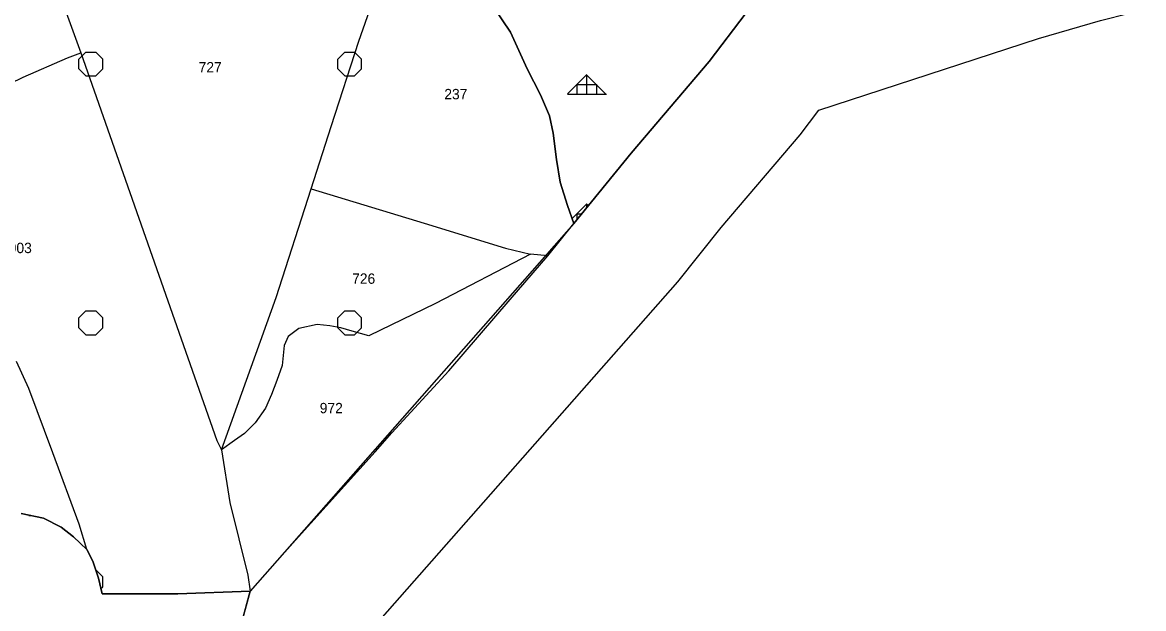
# Model space of a CAD drawing. Extents: x 410727 to 412947, y 4463506 to 4466382.
# Drawn here: x 412194.6 to 412627.7, y 4465187.2 to 4465413.6 of the extents above; entities that cross this region are included whole.
import ezdxf

# ---------------------------------------------------------------- set-up
doc = ezdxf.new("R2010")
doc.units = 0
for name, color, linetype in [('ADAKENARI', 7, 'Continuous'), ('KDS_PARSEL_NO', 7, 'Continuous'), ('KDS_PL', 7, 'Continuous'), ('PL_AYA_ORMAN', 7, 'Continuous'), ('PL_KA_TARIM_DIGER', 7, 'Continuous'), ('SN_ILCE', 7, 'Continuous'), ('TR_ORMAN', 7, 'Continuous'), ('TR_TARIMALANI', 7, 'Continuous')]:
    doc.layers.add(name, color=color, linetype=linetype)

msp = doc.modelspace()

# ---------------------------------------------------------------- linework, layer by layer
at = {"layer": 'ADAKENARI'}
for p, q in [((412383.18, 4465409.86), (412376.38, 4465419.67)), ((412474.23, 4465417.27), (412459.9, 4465398.41)), ((412389.57, 4465395.65), (412383.18, 4465409.86)), ((412394.76, 4465385.64), (412389.57, 4465395.65)), ((412459.9, 4465398.41), (412429.8, 4465363.06)), ((412398.16, 4465377.43), (412394.76, 4465385.64)), ((412399.56, 4465370.83), (412398.16, 4465377.43)), ((412400.96, 4465360.62), (412399.56, 4465370.83)), ((412429.8, 4465363.06), (412407.65, 4465335.86)), ((412402.36, 4465351.81), (412400.96, 4465360.62)), ((412405.15, 4465342.8), (412402.36, 4465351.81)), ((412407.65, 4465335.86), (412405.15, 4465342.8)), ((412407.65, 4465335.86), (412282.53, 4465193.95)), ((412194.07, 4465223.96), (412202.76, 4465222.11)), ((412202.76, 4465222.11), (412209.6, 4465218.57)), ((412209.6, 4465218.57), (412214.26, 4465214.94)), ((412214.26, 4465214.94), (412219.45, 4465209.95)), ((412219.45, 4465209.95), (412221.84, 4465205.46)), ((412221.84, 4465205.46), (412223.93, 4465198.88)), ((412223.93, 4465198.88), (412225.42, 4465192.89)), ((412225.42, 4465192.89), (412233.18, 4465192.89)), ((412233.18, 4465192.89), (412254.68, 4465192.89)), ((412282.53, 4465193.95), (412241.76, 4465042.59)), ((412254.68, 4465192.89), (412282.53, 4465193.95))]:
    msp.add_line(p, q, dxfattribs=at)
at = {"layer": 'KDS_PL'}
for p, q in [((412324.53, 4465406.29), (412338.85, 4465447.1)), ((412203.85, 4465438.37), (412217.2, 4465401.77)), ((412376.38, 4465419.67), (412383.18, 4465409.86)), ((412459.9, 4465398.41), (412474.23, 4465417.27)), ((412383.18, 4465409.86), (412389.57, 4465395.65)), ((412313.85, 4465373.37), (412324.53, 4465406.29)), ((412211.99, 4465399.9), (412217.2, 4465401.77)), ((412217.2, 4465401.77), (412269.72, 4465252.13)), ((412194.87, 4465392.45), (412211.99, 4465399.9)), ((412389.57, 4465395.65), (412394.76, 4465385.64)), ((412429.8, 4465363.06), (412459.9, 4465398.41)), ((412173.4, 4465382.13), (412194.87, 4465392.45)), ((412394.76, 4465385.64), (412398.16, 4465377.43)), ((412398.16, 4465377.43), (412399.56, 4465370.83)), ((412306.1, 4465349.26), (412313.85, 4465373.37)), ((412399.56, 4465370.83), (412400.96, 4465360.62)), ((412407.65, 4465335.86), (412429.8, 4465363.06)), ((412400.96, 4465360.62), (412402.36, 4465351.81)), ((412292.59, 4465307.34), (412306.1, 4465349.26)), ((412306.1, 4465349.26), (412349.76, 4465335.98)), ((412402.36, 4465351.81), (412405.15, 4465342.8)), ((412405.15, 4465342.8), (412407.65, 4465335.86)), ((412349.76, 4465335.98), (412381.2, 4465326.34)), ((412397.58, 4465323.48), (412407.65, 4465335.86)), ((412390.82, 4465324), (412354.18, 4465304.99)), ((412381.2, 4465326.34), (412390.82, 4465324)), ((412383.02, 4465306.56), (412397.58, 4465323.48)), ((412397.58, 4465323.48), (412390.82, 4465324)), ((412271.53, 4465248.49), (412292.59, 4465307.34)), ((412354.18, 4465304.99), (412328.45, 4465292.49)), ((412359.37, 4465278.95), (412383.02, 4465306.56)), ((412308.44, 4465296.92), (412301.42, 4465295.36)), ((412313.38, 4465296.4), (412308.44, 4465296.92)), ((412317.53, 4465295.62), (412313.38, 4465296.4)), ((412297.26, 4465292.23), (412295.7, 4465288.85)), ((412301.42, 4465295.36), (412297.26, 4465292.23)), ((412321.95, 4465294.32), (412317.53, 4465295.62)), ((412328.45, 4465292.49), (412321.95, 4465294.32)), ((412295.7, 4465288.85), (412294.92, 4465281.04)), ((412197.06, 4465272.17), (412192.28, 4465282.65)), ((412294.92, 4465281.04), (412292.85, 4465275.31)), ((412337.28, 4465255), (412359.37, 4465278.95)), ((412292.85, 4465275.31), (412290.77, 4465269.84)), ((412206.31, 4465247.34), (412197.06, 4465272.17)), ((412290.77, 4465269.84), (412288.43, 4465264.63)), ((412288.43, 4465264.63), (412284.53, 4465258.9)), ((412284.53, 4465258.9), (412280.37, 4465254.74)), ((412280.37, 4465254.74), (412276.47, 4465252.13)), ((412330.79, 4465247.71), (412337.28, 4465255)), ((412269.72, 4465252.13), (412271.53, 4465248.49)), ((412276.47, 4465252.13), (412271.53, 4465248.49)), ((412271.53, 4465248.49), (412274.65, 4465228.18)), ((412216.46, 4465219.82), (412206.31, 4465247.34)), ((412300.12, 4465213.59), (412330.79, 4465247.71)), ((412274.65, 4465228.18), (412281.67, 4465200.05)), ((412194.07, 4465223.96), (412202.76, 4465222.11)), ((412202.76, 4465222.11), (412209.6, 4465218.57)), ((412209.6, 4465218.57), (412214.26, 4465214.94)), ((412219.45, 4465209.95), (412216.46, 4465219.82)), ((412214.26, 4465214.94), (412219.45, 4465209.95)), ((412221.84, 4465205.46), (412219.45, 4465209.95)), ((412282.53, 4465193.95), (412300.12, 4465213.59)), ((412223.93, 4465198.88), (412221.84, 4465205.46)), ((412225.42, 4465192.89), (412223.93, 4465198.88)), ((412281.67, 4465200.05), (412282.53, 4465193.95)), ((412233.18, 4465192.89), (412225.42, 4465192.89)), ((412254.68, 4465192.89), (412233.18, 4465192.89)), ((412282.53, 4465193.95), (412241.76, 4465042.59)), ((412282.53, 4465193.95), (412254.68, 4465192.89))]:
    msp.add_line(p, q, dxfattribs=at)
at = {"layer": 'PL_AYA_ORMAN'}
for points in [[(412376.38, 4465419.67), (412383.18, 4465409.86), (412389.57, 4465395.65), (412394.76, 4465385.64), (412398.16, 4465377.43), (412399.56, 4465370.83), (412400.96, 4465360.62), (412402.36, 4465351.81), (412405.15, 4465342.8), (412407.65, 4465335.86), (412429.8, 4465363.06), (412459.9, 4465398.41), (412474.23, 4465417.27)], [(412152.99, 4464703.96), (412205.5, 4464903.47), (412241.76, 4465042.59), (412282.53, 4465193.95), (412254.68, 4465192.89), (412233.18, 4465192.89), (412225.42, 4465192.89), (412223.93, 4465198.88), (412221.84, 4465205.46), (412219.45, 4465209.95), (412214.26, 4465214.94), (412209.6, 4465218.57), (412202.76, 4465222.11), (412194.07, 4465223.96)]]:
    msp.add_lwpolyline(points, dxfattribs=at)
at = {"layer": 'PL_KA_TARIM_DIGER'}
msp.add_lwpolyline([(412376.38, 4465419.67), (412383.18, 4465409.86), (412389.57, 4465395.65), (412394.76, 4465385.64), (412398.16, 4465377.43), (412399.56, 4465370.83), (412400.96, 4465360.62), (412402.36, 4465351.81), (412405.15, 4465342.8), (412407.65, 4465335.86), (412282.53, 4465193.95), (412254.68, 4465192.89), (412233.18, 4465192.89), (412225.42, 4465192.89), (412223.93, 4465198.88), (412221.84, 4465205.46), (412219.45, 4465209.95), (412214.26, 4465214.94), (412209.6, 4465218.57), (412202.76, 4465222.11), (412194.07, 4465223.96)], dxfattribs=at)
at = {"layer": 'SN_ILCE'}
msp.add_lwpolyline([(412193.9, 4464682.62), (412249.03, 4464892.07), (412285.26, 4465031.06), (412323.25, 4465172.08), (412447.79, 4465313.34), (412464.51, 4465334.41), (412494.98, 4465370.19), (412502.22, 4465379.72), (412587.08, 4465407.4), (412611.01, 4465414.33), (412655.81, 4465425.78), (412681.09, 4465432.26), (412743.2, 4465445.25), (412753.52, 4465488.83), (412762.98, 4465515.83), (412772.34, 4465544.57), (412788.73, 4465589.26), (412798.93, 4465619.33), (412812.47, 4465658.52), (412814.31, 4465679.77), (412846.88, 4465686.61), (412891.91, 4465700.22), (412906.57, 4465708.44), (412915.37, 4465718.09)], dxfattribs=at)
at = {"layer": 'TR_ORMAN'}
for p, q in [((412405.16, 4465385.97), (412412.66, 4465393.47)), ((412405.16, 4465385.97), (412412.66, 4465393.47)), ((412420.02, 4465385.89), (412412.52, 4465393.38)), ((412420.02, 4465385.89), (412412.52, 4465393.38)), ((412412.67, 4465385.86), (412412.67, 4465393.36)), ((412412.67, 4465385.86), (412412.67, 4465393.36)), ((412408.92, 4465385.86), (412408.92, 4465389.61)), ((412408.92, 4465389.61), (412416.42, 4465389.61)), ((412408.92, 4465385.86), (412408.92, 4465389.61)), ((412408.92, 4465389.61), (412416.42, 4465389.61)), ((412416.42, 4465385.86), (412416.42, 4465389.61)), ((412416.42, 4465385.86), (412416.42, 4465389.61)), ((412405.17, 4465385.86), (412420.17, 4465385.86)), ((412405.17, 4465385.86), (412420.17, 4465385.86)), ((412406.96, 4465337.78), (412412.66, 4465343.47)), ((412406.96, 4465337.78), (412412.66, 4465343.47)), ((412408.92, 4465337.41), (412408.92, 4465339.61)), ((412408.92, 4465339.61), (412410.71, 4465339.61)), ((412408.92, 4465337.41), (412408.92, 4465339.61)), ((412408.92, 4465339.61), (412410.71, 4465339.61)), ((412413.22, 4465342.69), (412412.55, 4465343.36)), ((412413.22, 4465342.69), (412412.55, 4465343.36)), ((412412.67, 4465342.02), (412412.67, 4465343.36)), ((412412.67, 4465342.02), (412412.67, 4465343.36)), ((412197.11, 4465222.99), (412197.38, 4465223.26)), ((412197.11, 4465222.99), (412197.38, 4465223.26)), ((412197.11, 4465222.99), (412197.38, 4465223.26)), ((412197.11, 4465222.99), (412197.38, 4465223.26)), ((412197.12, 4465223.09), (412198.17, 4465223.09)), ((412197.12, 4465223.09), (412198.17, 4465223.09)), ((412197.12, 4465223.09), (412198.17, 4465223.09)), ((412197.12, 4465223.09), (412198.17, 4465223.09))]:
    msp.add_line(p, q, dxfattribs=at)
at = {"layer": 'TR_TARIMALANI'}
for p, q in [((412216.37, 4465399.43), (412219.08, 4465402.14)), ((412216.37, 4465399.43), (412219.08, 4465402.14)), ((412219.08, 4465402.14), (412222.91, 4465402.14)), ((412219.08, 4465402.14), (412222.91, 4465402.14)), ((412225.62, 4465399.43), (412222.91, 4465402.14)), ((412225.62, 4465399.43), (412222.91, 4465402.14)), ((412316.37, 4465399.43), (412319.08, 4465402.14)), ((412316.37, 4465399.43), (412319.08, 4465402.14)), ((412319.08, 4465402.14), (412322.91, 4465402.14)), ((412319.08, 4465402.14), (412322.91, 4465402.14)), ((412325.62, 4465399.43), (412322.91, 4465402.14)), ((412325.62, 4465399.43), (412322.91, 4465402.14)), ((412216.37, 4465395.6), (412216.37, 4465399.43)), ((412216.37, 4465395.6), (412216.37, 4465399.43)), ((412225.62, 4465395.6), (412225.62, 4465399.43)), ((412225.62, 4465395.6), (412225.62, 4465399.43)), ((412316.37, 4465395.6), (412316.37, 4465399.43)), ((412316.37, 4465395.6), (412316.37, 4465399.43)), ((412325.62, 4465395.6), (412325.62, 4465399.43)), ((412325.62, 4465395.6), (412325.62, 4465399.43)), ((412219.08, 4465392.89), (412216.37, 4465395.6)), ((412219.08, 4465392.89), (412216.37, 4465395.6)), ((412219.08, 4465392.89), (412222.91, 4465392.89)), ((412219.08, 4465392.89), (412222.91, 4465392.89)), ((412222.91, 4465392.89), (412225.62, 4465395.6)), ((412222.91, 4465392.89), (412225.62, 4465395.6)), ((412319.08, 4465392.89), (412316.37, 4465395.6)), ((412319.08, 4465392.89), (412316.37, 4465395.6)), ((412319.08, 4465392.89), (412322.91, 4465392.89)), ((412319.08, 4465392.89), (412322.91, 4465392.89)), ((412322.91, 4465392.89), (412325.62, 4465395.6)), ((412322.91, 4465392.89), (412325.62, 4465395.6)), ((412216.37, 4465299.43), (412219.08, 4465302.14)), ((412216.37, 4465299.43), (412219.08, 4465302.14)), ((412219.08, 4465302.14), (412222.91, 4465302.14)), ((412219.08, 4465302.14), (412222.91, 4465302.14)), ((412225.62, 4465299.43), (412222.91, 4465302.14)), ((412225.62, 4465299.43), (412222.91, 4465302.14)), ((412316.37, 4465299.43), (412319.08, 4465302.14)), ((412316.37, 4465299.43), (412319.08, 4465302.14)), ((412319.08, 4465302.14), (412322.91, 4465302.14)), ((412319.08, 4465302.14), (412322.91, 4465302.14)), ((412325.62, 4465299.43), (412322.91, 4465302.14)), ((412325.62, 4465299.43), (412322.91, 4465302.14)), ((412216.37, 4465295.6), (412216.37, 4465299.43)), ((412216.37, 4465295.6), (412216.37, 4465299.43)), ((412225.62, 4465295.6), (412225.62, 4465299.43)), ((412225.62, 4465295.6), (412225.62, 4465299.43)), ((412316.37, 4465295.6), (412316.37, 4465299.43)), ((412316.37, 4465295.6), (412316.37, 4465299.43)), ((412325.62, 4465295.6), (412325.62, 4465299.43)), ((412325.62, 4465295.6), (412325.62, 4465299.43)), ((412219.08, 4465292.89), (412216.37, 4465295.6)), ((412219.08, 4465292.89), (412216.37, 4465295.6)), ((412219.08, 4465292.89), (412222.91, 4465292.89)), ((412219.08, 4465292.89), (412222.91, 4465292.89)), ((412222.91, 4465292.89), (412225.62, 4465295.6)), ((412222.91, 4465292.89), (412225.62, 4465295.6)), ((412319.08, 4465292.89), (412316.37, 4465295.6)), ((412319.08, 4465292.89), (412316.37, 4465295.6)), ((412319.08, 4465292.89), (412322.91, 4465292.89)), ((412319.08, 4465292.89), (412322.91, 4465292.89)), ((412322.91, 4465292.89), (412325.62, 4465295.6)), ((412322.91, 4465292.89), (412325.62, 4465295.6)), ((412222.89, 4465202.14), (412222.91, 4465202.14)), ((412222.89, 4465202.14), (412222.91, 4465202.14)), ((412225.62, 4465199.43), (412222.91, 4465202.14)), ((412225.62, 4465199.43), (412222.91, 4465202.14)), ((412225.62, 4465195.6), (412225.62, 4465199.43)), ((412225.62, 4465195.6), (412225.62, 4465199.43)), ((412224.92, 4465194.91), (412225.62, 4465195.6)), ((412224.92, 4465194.91), (412225.62, 4465195.6))]:
    msp.add_line(p, q, dxfattribs=at)

# ---------------------------------------------------------------- texts
at = {"layer": 'KDS_PARSEL_NO'}
for s, p in [('727', (412262.66, 4465394.26)), ('237', (412357.56, 4465383.88)), ('903', (412189.29, 4465324.47)), ('726', (412321.95, 4465312.62)), ('972', (412309.44, 4465262.63))]:
    msp.add_text(s, height=4, dxfattribs=at).set_placement(p)

doc.saveas('drawing.dxf')
